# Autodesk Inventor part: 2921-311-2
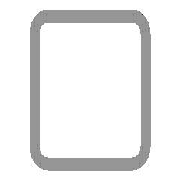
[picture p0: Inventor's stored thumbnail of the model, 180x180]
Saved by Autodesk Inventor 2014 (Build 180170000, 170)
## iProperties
IsCustomPart: 1
Company: NHTSA/VRTC
Created: 2012-02
Part Number: 2921-311-2
Material: Steel, Mild
Description: BENCH FRAME TUBE #2
Document SubType Name: Modeling
Standard: AISC
Designer: Dave Walker
Standards Organization: ANSI
Language: en-US
Size Designation: 1-1/2x1-1/2x1/8 - 24.56
Categories: <MemberInstance><Categories><Category DisplayName="Structural Shapes" InternalName="089c4875-fa83-4c05-b084-43b9cc11f5ed" Mnemonic="GRDR"><CategoryParameter Dis
Stock Number: T.S. 1 1/2 x 1 1/2 x 1/8 x 623.8mm (24.56")
Density: 1 g/cm^3
Project: CHILD SIDE IMPACT SLED
Appearance: Steel
G_L: 24.560 in
Author: Dave Walker
Title: Bench Frame Tube #2
Subject: Child Side Impact Sled
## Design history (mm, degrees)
node "Start plane"
node "End plane"
sketch "Sketch"
  geometry: L1 (-19.05, -12.7)-(-19.05, 12.7); L2 (-12.7, 19.05)-(12.7, 19.05); L3 (19.05, 12.7)-(19.05, -12.7); L4 (12.7, -19.05)-(-12.7, -19.05); L5 (-12.7, 15.875)-(12.7, 15.875); L6 (15.875, 12.7)-(15.875, -12.7); L7 (12.7, -15.875)-(-12.7, -15.875); L8 (-15.875, -12.7)-(-15.875, 12.7); L9 (0, 36.948)-(0, -36.948) reference; L10 (-23.079, 0)-(23.079, 0) reference; A1 r 6.35 centre (-12.7, -12.7) between (-19.05, -12.7) and (-12.7, -19.05); A2 r 6.35 centre (-12.7, 12.7) between (-12.7, 19.05) and (-19.05, 12.7); A3 r 6.35 centre (12.7, 12.7) between (19.05, 12.7) and (12.7, 19.05); A4 r 6.35 centre (12.7, -12.7) between (12.7, -19.05) and (19.05, -12.7); A5 r 3.175 centre (-12.7, 12.7) between (-12.7, 15.875) and (-15.875, 12.7); A6 r 3.175 centre (12.7, 12.7) between (15.875, 12.7) and (12.7, 15.875); A7 r 3.175 centre (12.7, -12.7) between (12.7, -15.875) and (15.875, -12.7); A8 r 3.175 centre (-12.7, -12.7) between (-15.875, -12.7) and (-12.7, -15.875)
  constraints: 16 end point, 16 point on circle, 8 centre point, 8 tangent, 4 parallel, 3 equal radius, 2 perpendicular, 7 other
  dimensions: "d10" = 38.1 distance between parallel lines of L2 L4 (= G_H); "d11" = 38.1 distance between parallel lines of L1 L3 (= G_W); "d12" = 3.175 distance between parallel lines of L3 L6 (= G_T); "d15" = 19.05 distance between parallel lines of L2 L10 (= 0.5 x d10); "d16" = 19.05 distance between parallel lines of L9 L3 (= 0.5 x d11); "d17" = 6.35 radius of A1 (= G_IR)
extrude "Body" new body sketch "Sketch" stored distance "d3" = 623.824 (= G_L); taper "d4" = 0 deg
node "Driven Length"
  sketch "Sketch3"
    geometry: L1 (0, 0)-(10, 0) reference
    constraints: 2 end point, 1 horizontal
  workplane "Work Plane3"
  sketch "Sketch4"
    geometry: L1 (-2, 0)-(12, 0) reference; L2 (-2, 623.824)-(12, 623.824) reference
    dimensions: "d19" = 623.824 distance between parallel lines of L1 L2 (derived)
body "Solid1"
other parameters: "G_W" = 38.1 [user parameter; used in 1 equation term], "G_H" = 38.1 [user parameter; used in 1 equation term], "G_T" = 3.175 [user parameter; used in 1 equation term], "G_IR" = 6.35 [user parameter; used in 1 equation term], "G_L" = 623.824 (= d19) [user parameter; used in 1 equation term], "G_OFFSET_START" = 0 [user parameter; used in 1 equation term], "G_OFFSET_END" = 0 [user parameter; used in 1 equation term], "d13" = 0 (computed from G_OFFSET_START), "d14" = 623.824 (= G_OFFSET_END + B_L), "B_L" = 623.824 [user parameter; used in 1 equation term], "d18" = 90 deg
